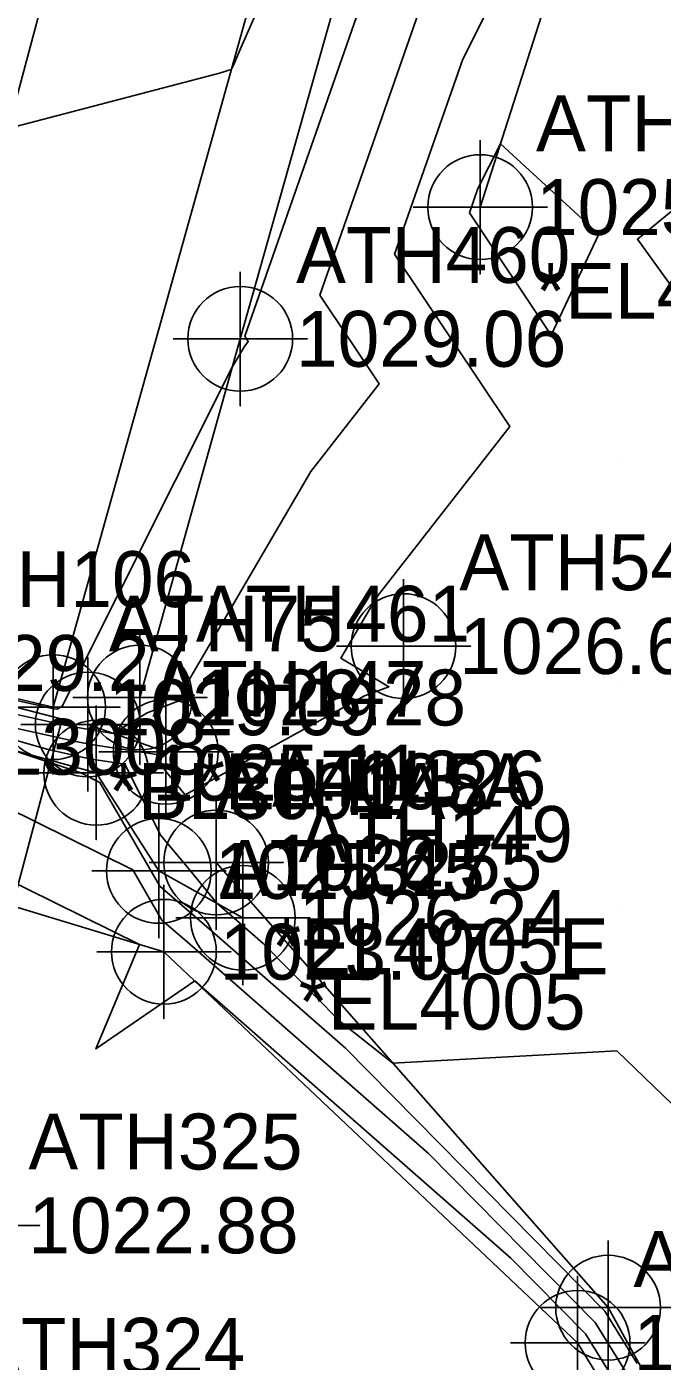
# Model space of a CAD drawing. Extents: x 1213164 to 1213550, y 766120 to 766870.
# Drawn here: x 1213343.4 to 1213371.8, y 766479.8 to 766539.5 of the extents above; entities that cross this region are included whole.
import ezdxf

# ---------------------------------------------------------------- set-up
doc = ezdxf.new("R2010")
doc.units = 0
for name, color, linetype in [('Default', 7, 'Continuous'), ('Exist DTM Breakline', 7, 'Continuous'), ('Exist DTM Breakline Cogo Comment', 7, 'Continuous'), ('Exist DTM Breakline Cogo Elevation', 7, 'Continuous'), ('Exist DTM Breakline Cogo Number', 7, 'Continuous'), ('Exist DTM Breakline Cogo Point CELL', 7, 'Continuous'), ('Exist DTM Crownline', 7, 'Continuous'), ('Exist DTM Crownline Cogo Comment', 7, 'Continuous'), ('Exist DTM Crownline Cogo Elevation', 7, 'Continuous'), ('Exist DTM Crownline Cogo Number', 7, 'Continuous'), ('Exist DTM Drainline Cogo Elevation', 7, 'Continuous'), ('Exist DTM Drainline Cogo Number', 7, 'Continuous'), ('Exist DTM Drainline Cogo Point CELL', 7, 'Continuous'), ('Exist DTM QL2 LIDAR Elevation Point', 7, 'Continuous'), ('Exist DTM Regular Point CELL', 7, 'Continuous'), ('Exist DTM Regular Point Cogo Elevation', 7, 'Continuous'), ('Exist DTM Regular Point Cogo Number', 7, 'Continuous'), ('Exist DTM Regular Point Underwater CELL', 7, 'Continuous'), ('Exist DTM Regular Point Underwater Cogo Elevation', 7, 'Continuous'), ('Exist DTM Regular Point Underwater Cogo Number', 7, 'Continuous'), ('Exist Hydro Stream or Body of Water', 7, 'Continuous'), ('Exist Roads EOP', 7, 'Continuous'), ('Exist Roads EOP Cogo Comment', 7, 'Continuous'), ('Exist Roads EOP Cogo Elevation', 7, 'Continuous'), ('Exist Roads EOP Cogo Number', 7, 'Continuous'), ('Exist Roads EOP Cogo Point CELL', 7, 'Continuous'), ('Exist Structure Major Bridge WW Cogo Point CELL', 7, 'Continuous'), ('Exist Structure Major Deck Tunnel Box Culvert', 7, 'Continuous')]:
    doc.layers.add(name, color=color, linetype=linetype)

msp = doc.modelspace()

# ---------------------------------------------------------------- linework, layer by layer
at = {"layer": 'Default'}
for points in [[(1213338.026, 766545.563), (1213342.554, 766534.959), (1213352.005, 766537.439), (1213352.534, 766537.592), (1213352.635, 766537.795), (1213353.026, 766538.706), (1213360.065, 766554.633)], [(1213332.007, 766541.892), (1213329.931, 766530.39), (1213327.288, 766514.12), (1213327, 766513.422), (1213327.863, 766513.073), (1213335.576, 766511.086), (1213336.81, 766510.732), (1213344.6, 766509), (1213344.738, 766508.974), (1213344.969, 766509.109), (1213352.579, 766524.276), (1213353.118, 766525.201), (1213353.296, 766525.429), (1213353.142, 766525.661), (1213361.519, 766549.652)], [(1213329.521, 766546.518), (1213328.953, 766537.116), (1213324.533, 766519.114), (1213324.485, 766518.851), (1213324.455, 766518.529), (1213324.436, 766517.95), (1213323.889, 766516.593), (1213323.629, 766514.207), (1213326.375, 766513.206), (1213327.431, 766512.78), (1213333.408, 766511.239), (1213339.3, 766509.55), (1213345.088, 766508.264), (1213346.155, 766508.062), (1213347.253, 766507.894), (1213348.774, 766508.818), (1213350.878, 766509.604), (1213350.411, 766509.881), (1213356.086, 766519.612), (1213359.141, 766523.529), (1213356.49, 766527.5), (1213362.202, 766543.858)], [(1213341.791, 766508.368), (1213345.575, 766507.527), (1213346.273, 766507.395), (1213349.198, 766506.95), (1213349.556, 766506.244), (1213350.478, 766505.15), (1213358.497, 766509.577), (1213359.582, 766509.982), (1213357.439, 766511.254), (1213359.055, 766514.024), (1213364.986, 766521.63), (1213359.838, 766529.34), (1213362.884, 766538.065), (1213366.855, 766545.969)], [(1213372.553, 766527.447), (1213370.697, 766530), (1213380, 766537.646)], [(1213368.972, 766530.234), (1213364.569, 766534.265), (1213363.567, 766532.271), (1213363.186, 766531.179), (1213366.841, 766525.705), (1213368.972, 766530.234)], [(1213303.87, 766518.54), (1213305.741, 766517.54), (1213317.218, 766513.237), (1213320.077, 766517.095), (1213320.94, 766518.61), (1213321.096, 766518.242), (1213321.058, 766517.826), (1213321.557, 766516.911), (1213321.492, 766514.928), (1213321.226, 766514.269), (1213325.513, 766512.129), (1213325.997, 766511.953), (1213326.133, 766511.898), (1213326.906, 766511.699), (1213342.392, 766507.26), (1213345.801, 766506.125), (1213346.659, 766505.701), (1213349.337, 766501.052), (1213351.669, 766499.048), (1213357.648, 766493.804), (1213369.246, 766482.036), (1213370.687, 766479.709)], [(1213300.885, 766515.957), (1213316.743, 766510.012), (1213318.331, 766512.154), (1213319.064, 766511.902), (1213321.218, 766513.267), (1213325.627, 766510.661), (1213339.551, 766506.025), (1213348.137, 766501.785), (1213349.431, 766499.539), (1213350.558, 766498.57), (1213361.343, 766489.111), (1213368.811, 766481.534), (1213374.658, 766472.092), (1213383.401, 766456.504), (1213384.24, 766453.245), (1213389.563, 766440.166), (1213389.659, 766438.461), (1213389.891, 766435.088), (1213390.675, 766420.964), (1213391.789, 766405.168), (1213396.624, 766394.628)], [(1213329.073, 766511.545), (1213344.281, 766507.187), (1213346.062, 766506.791), (1213346.39, 766506.729), (1213347.767, 766506.519), (1213349.386, 766503.329), (1213350.567, 766501.928), (1213351.889, 766500.291), (1213352.78, 766499.525), (1213353.953, 766498.497), (1213357.398, 766495.001), (1213359.756, 766493.143), (1213369.783, 766493.692), (1213376.375, 766487.335)], [(1213378.629, 766464.474), (1213368.376, 766481.032), (1213365.038, 766484.419), (1213350.897, 766496.821), (1213346.478, 766493.776), (1213348.434, 766498.453), (1213333.3, 766505.924), (1213325.062, 766508.667), (1213322.453, 766510.209), (1213318.62, 766507.782), (1213320.087, 766492.397), (1213319.595, 766488.556), (1213328.26, 766486.873), (1213325.345, 766484.153), (1213319.036, 766487.115), (1213317.521, 766487.959), (1213313.605, 766489.92), (1213302.155, 766491.681)]]:
    msp.add_lwpolyline(points, dxfattribs=at)
at = {"layer": 'Exist DTM Breakline'}
msp.add_line((1213346.114, 766508.293), (1213349.604, 766507.072), dxfattribs=at)
for points in [[(1213396.806, 766643.375), (1213385.246, 766629.794), (1213372.134, 766599.17), (1213360.99, 766554.137), (1213352.934, 766525.547), (1213348.45, 766509.498)], [(1213385.817, 766608.858), (1213377.005, 766573.098), (1213363.665, 766531.442)], [(1213323.087, 766522.479), (1213320.824, 766514.242), (1213325.941, 766511.767), (1213346.495, 766506.136), (1213349.294, 766501.74), (1213353.051, 766499.642)], [(1213458.364, 766304.665), (1213456.152, 766280.485), (1213457.947, 766246.9), (1213447.467, 766261.797), (1213441.278, 766307.974), (1213433.945, 766370.733), (1213403.815, 766386.389), (1213393.078, 766404.937), (1213391.083, 766440.453), (1213383.54, 766456.522), (1213369.388, 766482.2), (1213351.856, 766502.119)]]:
    msp.add_lwpolyline(points, dxfattribs=at)
at = {"layer": 'Exist DTM Breakline Cogo Point CELL'}
for points in [[(1213363.665, 766534.442), (1213363.665, 766528.442), (1213363.665, 766531.442), (1213366.665, 766531.442), (1213360.665, 766531.442)], [(1213352.934, 766528.547), (1213352.934, 766522.547), (1213352.934, 766525.547), (1213355.934, 766525.547), (1213349.934, 766525.547)], [(1213348.45, 766512.498), (1213348.45, 766506.498), (1213348.45, 766509.498), (1213351.45, 766509.498), (1213345.45, 766509.498)], [(1213346.495, 766509.136), (1213346.495, 766503.136), (1213346.495, 766506.136), (1213349.495, 766506.136), (1213343.495, 766506.136)], [(1213351.856, 766505.119), (1213351.856, 766499.119), (1213351.856, 766502.119), (1213354.856, 766502.119), (1213348.856, 766502.119)], [(1213349.294, 766504.74), (1213349.294, 766498.74), (1213349.294, 766501.74), (1213352.294, 766501.74), (1213346.294, 766501.74)], [(1213353.051, 766502.642), (1213353.051, 766496.642), (1213353.051, 766499.642), (1213356.051, 766499.642), (1213350.051, 766499.642)], [(1213369.388, 766485.2), (1213369.388, 766479.2), (1213369.388, 766482.2), (1213372.388, 766482.2), (1213366.388, 766482.2)]]:
    msp.add_lwpolyline(points, dxfattribs=at)
for centre in [(1213363.665, 766531.442), (1213352.934, 766525.547), (1213348.45, 766509.498), (1213346.495, 766506.136), (1213351.856, 766502.119), (1213349.294, 766501.74), (1213353.051, 766499.642), (1213369.388, 766482.2)]:
    msp.add_circle(centre, 2.344, dxfattribs=at)
at = {"layer": 'Exist DTM Crownline'}
msp.add_lwpolyline([(1213369.874, 766637.44), (1213360.318, 766601.875), (1213348.565, 766557.408), (1213336.15, 766511.045)], dxfattribs=at)
at = {"layer": 'Exist DTM Drainline Cogo Point CELL'}
for points in [[(1213349.519, 766501.124), (1213349.519, 766495.124), (1213349.519, 766498.124), (1213352.519, 766498.124), (1213346.519, 766498.124)], [(1213368.024, 766483.627), (1213368.024, 766477.627), (1213368.024, 766480.627), (1213371.024, 766480.627), (1213365.024, 766480.627)]]:
    msp.add_lwpolyline(points, dxfattribs=at)
for centre in [(1213349.519, 766498.124), (1213368.024, 766480.627)]:
    msp.add_circle(centre, 2.344, dxfattribs=at)
at = {"layer": 'Exist DTM QL2 LIDAR Elevation Point'}
for p, q in [((1213370, 766530), (1213370, 766530)), ((1213370, 766520), (1213370, 766520)), ((1213360, 766510), (1213360, 766510)), ((1213370, 766510), (1213370, 766510)), ((1213370, 766500), (1213370, 766500))]:
    msp.add_line(p, q, dxfattribs=at)
at = {"layer": 'Exist DTM Regular Point CELL'}
msp.add_lwpolyline([(1213360.236, 766514.8), (1213360.236, 766508.8), (1213360.236, 766511.8), (1213363.236, 766511.8), (1213357.236, 766511.8)], dxfattribs=at)
msp.add_circle((1213360.236, 766511.8), 2.344, dxfattribs=at)
at = {"layer": 'Exist DTM Regular Point Underwater CELL'}
msp.add_lwpolyline([(1213340.957, 766488.883), (1213340.957, 766482.883), (1213340.957, 766485.883), (1213343.957, 766485.883), (1213337.957, 766485.883)], dxfattribs=at)
at = {"layer": 'Exist Hydro Stream or Body of Water'}
msp.add_lwpolyline([(1213462.585, 766303.681), (1213457.242, 766280.725), (1213458.541, 766244.269), (1213446.982, 766261.332), (1213440.132, 766307.328), (1213429.645, 766367.831), (1213400.182, 766384.285), (1213389.875, 766405.51), (1213387.132, 766439.706), (1213382.822, 766456.43), (1213368.024, 766480.627), (1213349.519, 766498.124), (1213324.243, 766505.779)], dxfattribs=at)
at = {"layer": 'Exist Roads EOP'}
for points in [[(1213344.559, 766509.063), (1213357.658, 766555.924), (1213369.403, 766599.695), (1213380.499, 766635.509), (1213390.233, 766668.75)], [(1213327.952, 766513.134), (1213336.15, 766511.045), (1213344.559, 766509.063)]]:
    msp.add_lwpolyline(points, dxfattribs=at)
at = {"layer": 'Exist Roads EOP Cogo Point CELL'}
msp.add_lwpolyline([(1213344.559, 766512.063), (1213344.559, 766506.063), (1213344.559, 766509.063), (1213347.559, 766509.063), (1213341.559, 766509.063)], dxfattribs=at)
msp.add_circle((1213344.559, 766509.063), 2.344, dxfattribs=at)
at = {"layer": 'Exist Structure Major Bridge WW Cogo Point CELL'}
for points in [[(1213343.114, 766508.293), (1213349.114, 766508.293), (1213346.114, 766508.293), (1213346.114, 766511.293), (1213346.114, 766505.293)], [(1213346.604, 766507.072), (1213352.604, 766507.072), (1213349.604, 766507.072), (1213349.604, 766510.072), (1213349.604, 766504.072)]]:
    msp.add_lwpolyline(points, dxfattribs=at)
for centre in [(1213346.114, 766508.293), (1213349.604, 766507.072)]:
    msp.add_circle(centre, 2.344, dxfattribs=at)
at = {"layer": 'Exist Structure Major Deck Tunnel Box Culvert'}
msp.add_lwpolyline([(1213334.645, 766469.793), (1213316.583, 766474.725), (1213327.014, 766513.184), (1213344.974, 766508.526), (1213334.645, 766469.793)], dxfattribs=at)

# ---------------------------------------------------------------- texts
at = {"layer": 'Exist DTM Breakline Cogo Comment'}
for s, p in [('*EL4005', (1213366.165, 766526.442)), ('*EL4005A', (1213350.95, 766504.498)), ('*EL4005E', (1213354.356, 766497.119)), ('*EL4005', (1213355.551, 766494.642))]:
    msp.add_text(s, height=2.5, dxfattribs=at).set_placement(p)
at = {"layer": 'Exist DTM Breakline Cogo Elevation'}
for s, p in [('1025.86', (1213366.165, 766530.192)), ('1029.06', (1213355.434, 766524.297)), ('1028.28', (1213350.95, 766508.248)), ('1025.11', (1213348.995, 766504.886)), ('1026.55', (1213354.356, 766500.869)), ('1025.45', (1213351.794, 766500.49)), ('1026.24', (1213355.551, 766498.392))]:
    msp.add_text(s, height=2.5, dxfattribs=at).set_placement(p)
at = {"layer": 'Exist DTM Breakline Cogo Number'}
for s, p in [('ATH544', (1213366.165, 766533.942)), ('ATH460', (1213355.434, 766528.047)), ('ATH461', (1213350.95, 766511.998)), ('ATH147', (1213348.995, 766508.636)), ('ATH326', (1213354.356, 766504.619)), ('ATH148', (1213351.794, 766504.24)), ('ATH149', (1213355.551, 766502.142))]:
    msp.add_text(s, height=2.5, dxfattribs=at).set_placement(p)
at = {"layer": 'Exist DTM Crownline Cogo Comment'}
msp.add_text('*EL3008', height=2.5, dxfattribs=at).set_placement((1213338.65, 766506.045))
at = {"layer": 'Exist DTM Crownline Cogo Elevation'}
msp.add_text('1029.27', height=2.5, dxfattribs=at).set_placement((1213338.65, 766509.795))
at = {"layer": 'Exist DTM Crownline Cogo Number'}
msp.add_text('ATH106', height=2.5, dxfattribs=at).set_placement((1213338.65, 766513.545))
at = {"layer": 'Exist DTM Drainline Cogo Elevation'}
for s, p in [('1023.07', (1213352.019, 766496.874)), ('1022.19', (1213370.524, 766479.377))]:
    msp.add_text(s, height=2.5, dxfattribs=at).set_placement(p)
at = {"layer": 'Exist DTM Drainline Cogo Number'}
for s, p in [('ATH327', (1213352.019, 766500.624)), ('ATH319', (1213370.524, 766483.127))]:
    msp.add_text(s, height=2.5, dxfattribs=at).set_placement(p)
at = {"layer": 'Exist DTM Regular Point Cogo Elevation'}
msp.add_text('1026.60', height=2.5, dxfattribs=at).set_placement((1213362.736, 766510.55))
at = {"layer": 'Exist DTM Regular Point Cogo Number'}
msp.add_text('ATH545', height=2.5, dxfattribs=at).set_placement((1213362.736, 766514.3))
at = {"layer": 'Exist DTM Regular Point Underwater Cogo Elevation'}
msp.add_text('1022.88', height=2.5, dxfattribs=at).set_placement((1213343.457, 766484.633))
at = {"layer": 'Exist DTM Regular Point Underwater Cogo Number'}
for s, p in [('ATH325', (1213343.457, 766488.383)), ('ATH324', (1213340.892, 766479.244))]:
    msp.add_text(s, height=2.5, dxfattribs=at).set_placement(p)
at = {"layer": 'Exist Roads EOP Cogo Comment'}
msp.add_text('*BL3001A', height=2.5, dxfattribs=at).set_placement((1213347.059, 766504.063))
at = {"layer": 'Exist Roads EOP Cogo Elevation'}
msp.add_text('1029.09', height=2.5, dxfattribs=at).set_placement((1213347.059, 766507.813))
at = {"layer": 'Exist Roads EOP Cogo Number'}
msp.add_text('ATH75', height=2.5, dxfattribs=at).set_placement((1213347.059, 766511.563))

doc.saveas('drawing.dxf')
